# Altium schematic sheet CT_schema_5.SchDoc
size 391 x 238 mm
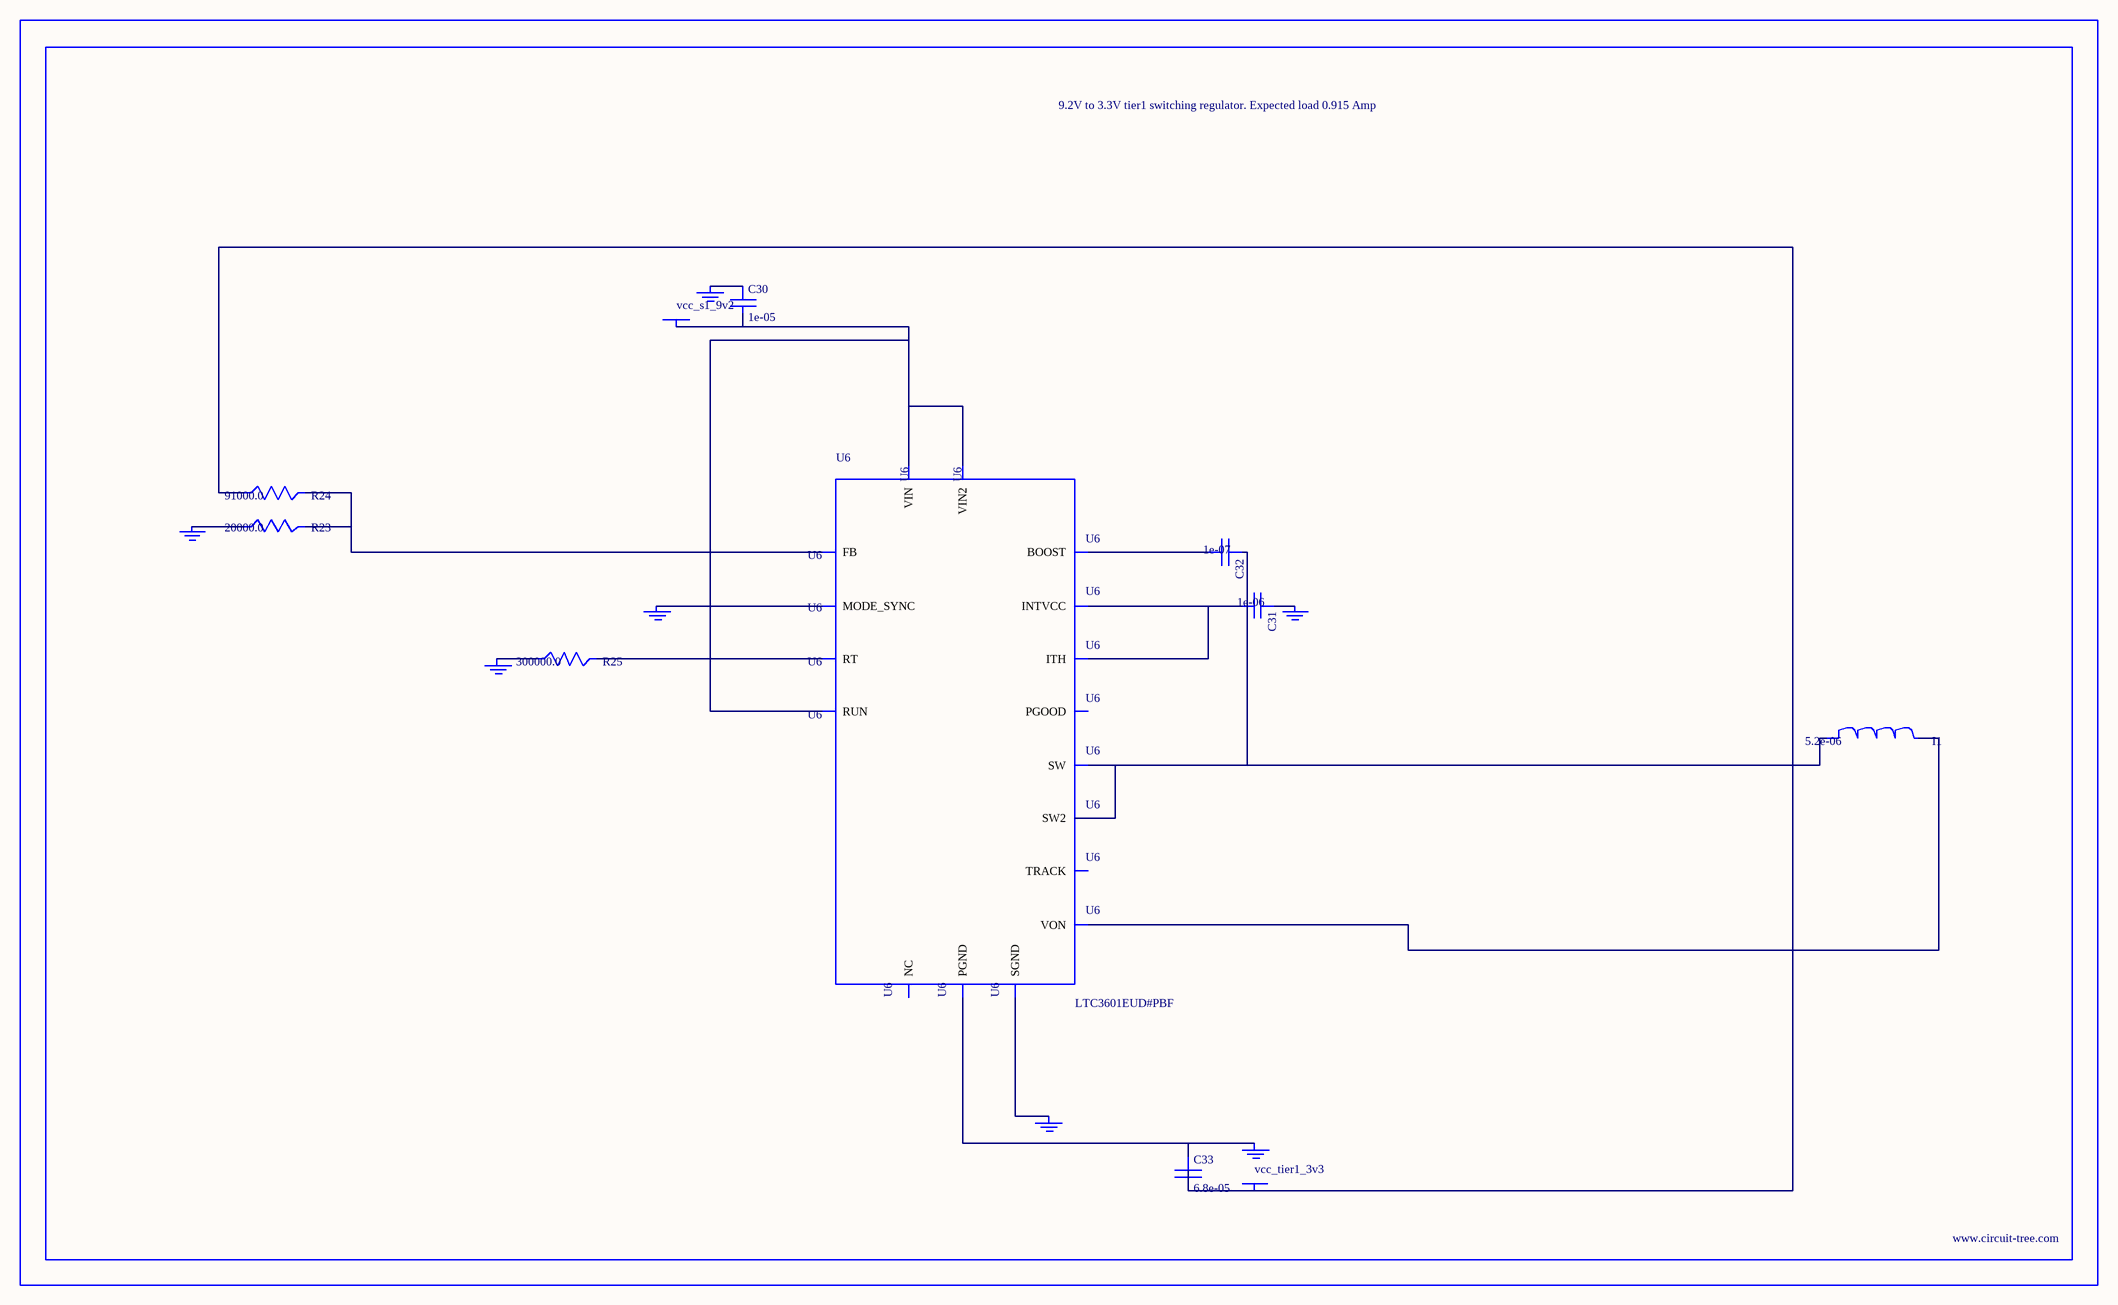
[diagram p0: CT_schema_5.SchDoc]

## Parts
BORDER4  (no value)
C30  1e-05  [C0805]
C31  1e-06  [C0603]
C32  1e-07  [C0402]
C33  6.8e-05  [2220]
GND_INSTANCE_4_0  (no value)
GND_INSTANCE_4_1  (no value)
GND_INSTANCE_4_2  (no value)
GND_INSTANCE_4_3  (no value)
GND_INSTANCE_4_4  (no value)
GND_INSTANCE_4_5  (no value)
GND_INSTANCE_4_6  (no value)
I1  5.2e-06  [DR1040]
POWER_INSTANCE_4_0  vcc_s1_9v2
POWER_INSTANCE_4_1  vcc_tier1_3v3
R23  20000.0  [R0603]
R24  91000.0  [R0603]
R25  300000.0  [R0603]
U6  LTC3601EUD#PBF  [QFN-16_EP]

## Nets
NetC30_1: C30.1 GND_INSTANCE_4_5.0(GND)
NetC30_2: C30.2 POWER_INSTANCE_4_0.0(PWR) U6.14(RUN) U6.15(VIN) U6.16(VIN2)
NetC31_1: C31.1 GND_INSTANCE_4_1.0(GND)
NetC31_2: C31.2 U6.7(INTVCC) U6.12(ITH)
NetC32_1: C32.1 I1.1 U6.3(SW) U6.4(SW2)
NetC32_2: C32.2 U6.6(BOOST)
NetC33_1: C33.1 GND_INSTANCE_4_6.0(GND) U6.17(PGND)
NetC33_2: C33.2 I1.2 POWER_INSTANCE_4_1.0(PWR) R24.1 U6.8(VON)
NetGND_INSTANCE_4_0_0: GND_INSTANCE_4_0.0(GND) U6.1(MODE_SYNC)
NetGND_INSTANCE_4_2_0: GND_INSTANCE_4_2.0(GND) U6.9(SGND)
NetGND_INSTANCE_4_3_0: GND_INSTANCE_4_3.0(GND) R25.1
NetGND_INSTANCE_4_4_0: GND_INSTANCE_4_4.0(GND) R23.1
NetR23_2: R23.2 R24.2 U6.11(FB)
NetR25_2: R25.2 U6.10(RT)

Not connected (* = marked no-connect by the designer): U6 2(PGOOD) 5(NC) 13(TRACK)

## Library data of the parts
BORDER4 = BORDER_PAGE4
C30 = C0805C106K8RACTU
C31 = C0603C105K3RACTU
C32 = C0402C104K3RACTU
C33 = C5750X5R1A686M
GND_INSTANCE_4_0-GND_INSTANCE_4_6 = GND
I1 = DR1040-5R2-R
POWER_INSTANCE_4_0 POWER_INSTANCE_4_1 = PWR
R23 = RC0603JR-0720KL
R24 = RC0603JR-0791KL
R25 = RC0603JR-07300KL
